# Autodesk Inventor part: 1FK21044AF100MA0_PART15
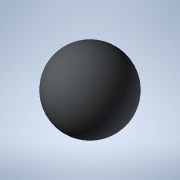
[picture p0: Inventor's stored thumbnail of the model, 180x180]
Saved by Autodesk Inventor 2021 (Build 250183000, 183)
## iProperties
Created: 2025-04
Part Number: 1FK21044AF100MA0_PART15
Material: Generic
Catalog Web Link: www.3dfindit.com
Description: -Servo synchronous motor
Document SubType Name: Modeling
Designer: psAdmin
Mass: 0.137258 g
Surface Area: 1.2868 cm^2
Volume: 0.137258 cm^3
Density: 1 g/cm^3
Appearance: PSOLRGB-212-217-219
Category: PARTsolutions
Title: 1FK21044AF100MA0_PART15
Author: Cadenas PARTsolutions
Comments: Servo synchronous motor
Sending System: PARTsolutions
Preprocessor: ST-DEVELOPER v19.3
PSOL_IDENT_0: {$CADENAS_DATA/23d-libs/siemens_ag/_cat_/ec/e4/1fk21044af100ma0.prj},216 {VTYP=3D},{NB=1FK21044AF100
PSOL_IDENT_1: MA0_PART15},{LINA=1FK21044AF100MA0_PART15},{NN=1FK21044AF100MA0_PART15},{NOPRJ=TRUE},{DATE=19.08.202
PSOL_IDENT_2: 5 14:01:05},{GEOMDATE=30.07.2025 02:01:01},{VERSION=},{LINEID=10},{WBVAR=},{WBNUMERIC=}  {NB=1FK2104
PSOL_IDENT_3: 4AF100MA0_PART15},{LINA=1FK21044AF100MA0_PART15},{KT=DUMMY},{PREVIEW=../../../_pool_/cb/72/p_d211_xx
PSOL_IDENT_4: _00434j.png},{DESCSHORT=SIMOTICS S-1FK2 HD, SINAMICS S210 3AC 400V-480V, 1.27 Nm, 3000 rpm},{DESCLON
PSOL_IDENT_5: G=SIMOTICS S-1FK2 HD servo motor M0=1.27 Nm; PN = 0.4 kW at nN=3000 rpm (380-480 V); PN = 0.2 kW at
PSOL_IDENT_6: nN=1500 rpm (200-240 V); with holding brake; degree of protection IP64; cylindrical shaft D19x40mm;
PSOL_IDENT_7: absolute encoder 22-bit + 12-bit multiturn (encoder AM22DQC); with OCC interface; plug size M17, rot
PSOL_IDENT_8: atable; SIMOTICS S-1FK2 servomotorfor a wide range of uses in industrial environments. SIMOTICS S‑1F
PSOL_IDENT_9: K2 servomotors are compact synchronous motors with a high dynamic performance that set themselves ap
PSOL_IDENT_10: art as a result of their high power density, degree of protection and overload capability. The motor
PSOL_IDENT_11: s are available in two variants: as High Dynamic variant (highest dynamic performance as a result of
PSOL_IDENT_12: the low intrinsic moment of inertia for applications demanding a high dynamic performance with low
PSOL_IDENT_13: moved masses) - and as Compact variant (precise and stable closed-loop control for medium up to larg
PSOL_IDENT_14: e moved masses as a result of a medium intrinsic moment of inertia). SIMOTICSS‑1FK2 servomotors full
PSOL_IDENT_15: y exploit their strengths in a system with the SINAMICSS210 frequency converter and simple connectio
PSOL_IDENT_16: n using the one cable connection (OCC). Advantages include the short control and positioning times,
PSOL_IDENT_17: fast and precise correction of disturbing quantities as well as stable control with a high dynamic p
PSOL_IDENT_18: erformance. The servo motors can be configured to address a wide range of requirements. For example
PSOL_IDENT_19: with and without holding brake, IP64 or IP65 degree of protection, singleturn or multiturn absolute
PSOL_IDENT_20: encoders - to name just a few. Further, the servomotors are available in different shaft heights ext
PSOL_IDENT_21: ending from 20 to 100. A shaft sealing ring is available to achieve an IP65 degree of protection and
PSOL_IDENT_22: for subsequent mounting at the motor or as spare part. SIMOTICS - the optimum motor for each and ev
PSOL_IDENT_23: ery motion control application.},{INTNO=195125043275},{SUPPLIERALTNO=1FK2104-4AF10-0MA0},{MANUID=1FK
PSOL_IDENT_24: 21044AF100MA0},{MANUNAME=Siemens},{MANUTYPEDESC=Synchronous motor 1FK2-HD 1.27 NM},{AAU732=SIMOTICS}
PSOL_IDENT_25: ,{AAO057=S-1FK2},{AAU734=SIMOTICS S-1FK2 HD servo motor M0=1.27 Nm; PN = 0.4 kW at nN=3000 rpm (380-
PSOL_IDENT_26: 480 V); PN = 0.2 kW at nN=1500 rpm (200-240 V); with holding brake; degree of protection IP64; cylin
PSOL_IDENT_27: drical shaft D19x40mm; absolute encoder 22-bit + 12-bit multiturn (encoder AM22DQC); with OCC interf
PSOL_IDENT_28: ace; plug size M17, rotatable;},{AAW338=Synchronous motor 1FK2-HD 1.27 NM},{AAO742=SIMOTICS},{AAO663=
PSOL_IDENT_29: 4042948694015},{NOCUPEROU=1},{PRICEQUANTITY=1},{QUANTITYMIN=1},{QUANTITYINT=1},{CTN=85015100},{COO=D
PSOL_IDENT_30: E},{AAO676=1FK2104-4AF10-0MA0},{AAO677=Siemens AG},{ORDERUNIT=C62},{CONTENTUNIT=C62}
NB: 1FK21044AF100MA0_PART15
NT: Servo synchronous motor
NBSYN: $MANUID._PART15
LINA: 1FK21044AF100MA0_PART15
CATALOG: SIEMENS
PREVIEW: ../../../_pool_/cb/72/p_d211_xx_00434j.png
DESCSHORT: SIMOTICS S-1FK2 HD, SINAMICS S210 3AC 400V-480V, 1.27 Nm, 3000 rpm
DESCLONG: SIMOTICS S-1FK2 HD servo motor M0=1.27 Nm; PN = 0.4 kW at nN=3000 rpm (380-480 V); PN = 0.2 kW at nN=1500 rpm (200-240 V); with holding brake; degree of protect
INTNO: 195125043275
SUPPLIERALTNO: 1FK2104-4AF10-0MA0
MANUID: 1FK21044AF100MA0
MANUNAME: Siemens
MANUTYPEDESC: Synchronous motor 1FK2-HD 1.27 NM
AAU732: SIMOTICS
AAO057: S-1FK2
AAU734: SIMOTICS S-1FK2 HD servo motor M0=1.27 Nm; PN = 0.4 kW at nN=3000 rpm (380-480 V); PN = 0.2 kW at nN=1500 rpm (200-240 V); with holding brake; degree of protect
AAW338: Synchronous motor 1FK2-HD 1.27 NM
AAO742: SIMOTICS
AAO663: 4042948694015.0
NOCUPEROU: 1
PRICEQUANTITY: 1
QUANTITYMIN: 1
QUANTITYINT: 1
CTN: 85015100
COO: DE
ARTICLENO: 1FK21044AF100MA0_PART15
BOMINFO: 1FK21044AF100MA0_PART15
CREATOR: CADENAS GmbH
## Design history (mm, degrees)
feature "2025_04_17_15_33_01_0673"
body "Solid1"
